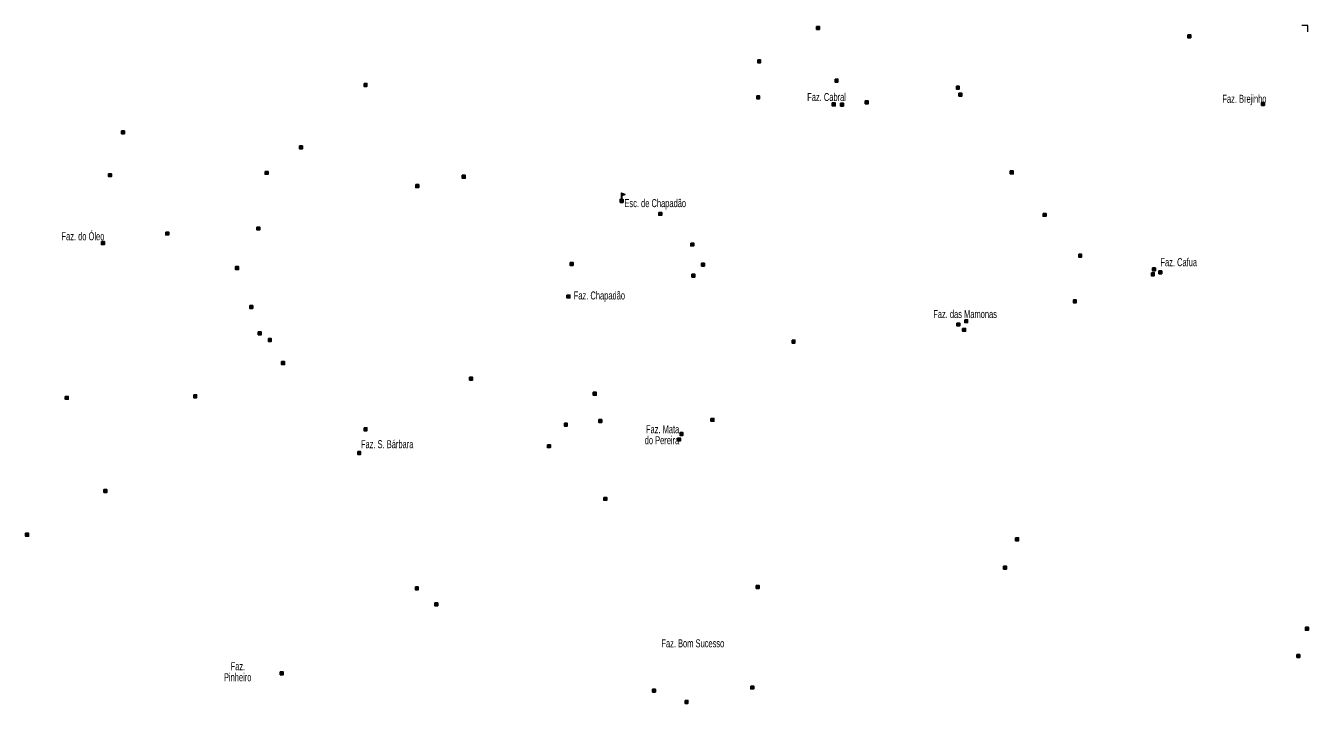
# Model space of a CAD drawing. Extents: x 447.8 to 473.9, y 7733.1 to 7760.8.
# Drawn here: x 461.07 to 473.9, y 7754.02 to 7760.8 of the extents above; entities that cross this region are included whole.
import ezdxf
from ezdxf.enums import TextEntityAlignment as Align

# ---------------------------------------------------------------- set-up
doc = ezdxf.new("R2010")
doc.units = 0
doc.header["$LTSCALE"] = 0.032
for name, color, linetype, lineweight in [('2', 7, 'Continuous', 25), ('4', 7, 'Continuous', 25), ('63', 7, 'Continuous', 13)]:
    doc.layers.add(name, color=color, linetype=linetype, lineweight=lineweight)
doc.layers.add('61', color=7, linetype='Continuous')

msp = doc.modelspace()

# ---------------------------------------------------------------- hatches: boundary and pattern name
at = {"layer": '2'}
for points in [[(468.9794, 7760.7919), (469.0084, 7760.7919), (469.0084, 7760.7629), (468.9794, 7760.7629)], [(472.691, 7760.7083), (472.72, 7760.7083), (472.72, 7760.6793), (472.691, 7760.6793)], [(468.3912, 7760.4577), (468.4202, 7760.4577), (468.4202, 7760.4287), (468.3912, 7760.4287)], [(469.1648, 7760.2655), (469.1938, 7760.2655), (469.1938, 7760.2365), (469.1648, 7760.2365)], [(464.4566, 7760.222), (464.4856, 7760.222), (464.4856, 7760.193), (464.4566, 7760.193)], [(470.3778, 7760.195), (470.4068, 7760.195), (470.4068, 7760.166), (470.3778, 7760.166)], [(468.382, 7760.0984), (468.411, 7760.0984), (468.411, 7760.0694), (468.382, 7760.0694)], [(469.1373, 7760.0274), (469.1663, 7760.0274), (469.1663, 7759.9984), (469.1373, 7759.9984)], [(469.2197, 7760.0251), (469.2487, 7760.0251), (469.2487, 7759.9961), (469.2197, 7759.9961)], [(469.4669, 7760.048), (469.4959, 7760.048), (469.4959, 7760.019), (469.4669, 7760.019)], [(470.4034, 7760.1247), (470.4324, 7760.1247), (470.4324, 7760.0957), (470.4034, 7760.0957)], [(473.4281, 7760.0321), (473.4571, 7760.0321), (473.4571, 7760.0031), (473.4281, 7760.0031)], [(462.0327, 7759.7482), (462.0617, 7759.7482), (462.0617, 7759.7192), (462.0327, 7759.7192)], [(463.8112, 7759.5971), (463.8402, 7759.5971), (463.8402, 7759.5681), (463.8112, 7759.5681)], [(461.9023, 7759.3202), (461.9313, 7759.3202), (461.9313, 7759.2912), (461.9023, 7759.2912)], [(463.4679, 7759.3431), (463.4969, 7759.3431), (463.4969, 7759.3141), (463.4679, 7759.3141)], [(465.4386, 7759.3041), (465.4676, 7759.3041), (465.4676, 7759.2751), (465.4386, 7759.2751)], [(470.9167, 7759.3473), (470.9457, 7759.3473), (470.9457, 7759.3183), (470.9167, 7759.3183)], [(464.9739, 7759.2103), (465.0029, 7759.2103), (465.0029, 7759.1813), (464.9739, 7759.1813)], [(467.4024, 7758.9334), (467.4314, 7758.9334), (467.4314, 7758.9044), (467.4024, 7758.9044)], [(471.2447, 7758.9234), (471.2737, 7758.9234), (471.2737, 7758.8944), (471.2447, 7758.8944)], [(462.4745, 7758.7365), (462.5035, 7758.7365), (462.5035, 7758.7075), (462.4745, 7758.7075)], [(463.3855, 7758.7869), (463.4145, 7758.7869), (463.4145, 7758.7579), (463.3855, 7758.7579)], [(461.8313, 7758.6404), (461.8603, 7758.6404), (461.8603, 7758.6114), (461.8313, 7758.6114)], [(467.7228, 7758.6266), (467.7518, 7758.6266), (467.7518, 7758.5976), (467.7228, 7758.5976)], [(471.6004, 7758.5145), (471.6294, 7758.5145), (471.6294, 7758.4855), (471.6004, 7758.4855)], [(463.1726, 7758.3909), (463.2016, 7758.3909), (463.2016, 7758.3619), (463.1726, 7758.3619)], [(466.5166, 7758.4321), (466.5456, 7758.4321), (466.5456, 7758.4031), (466.5166, 7758.4031)], [(467.8304, 7758.4252), (467.8594, 7758.4252), (467.8594, 7758.3962), (467.8304, 7758.3962)], [(472.3374, 7758.3781), (472.3664, 7758.3781), (472.3664, 7758.3491), (472.3374, 7758.3491)], [(472.4013, 7758.3483), (472.4303, 7758.3483), (472.4303, 7758.3193), (472.4013, 7758.3193)], [(467.7343, 7758.3154), (467.7633, 7758.3154), (467.7633, 7758.2864), (467.7343, 7758.2864)], [(472.3268, 7758.3292), (472.3558, 7758.3292), (472.3558, 7758.3002), (472.3268, 7758.3002)], [(466.4846, 7758.1071), (466.5136, 7758.1071), (466.5136, 7758.0781), (466.4846, 7758.0781)], [(463.3145, 7758.0018), (463.3435, 7758.0018), (463.3435, 7757.9728), (463.3145, 7757.9728)], [(471.5472, 7758.0587), (471.5762, 7758.0587), (471.5762, 7758.0297), (471.5472, 7758.0297)], [(470.3821, 7757.8265), (470.4111, 7757.8265), (470.4111, 7757.7975), (470.3821, 7757.7975)], [(470.4607, 7757.8602), (470.4897, 7757.8602), (470.4897, 7757.8312), (470.4607, 7757.8312)], [(463.3992, 7757.7386), (463.4282, 7757.7386), (463.4282, 7757.7096), (463.3992, 7757.7096)], [(470.4396, 7757.7732), (470.4686, 7757.7732), (470.4686, 7757.7442), (470.4396, 7757.7442)], [(463.4999, 7757.6722), (463.5289, 7757.6722), (463.5289, 7757.6432), (463.4999, 7757.6432)], [(468.7345, 7757.6562), (468.7635, 7757.6562), (468.7635, 7757.6272), (468.7345, 7757.6272)], [(463.6327, 7757.441), (463.6617, 7757.441), (463.6617, 7757.412), (463.6327, 7757.412)], [(465.5118, 7757.2854), (465.5408, 7757.2854), (465.5408, 7757.2564), (465.5118, 7757.2564)], [(461.4697, 7757.0931), (461.4987, 7757.0931), (461.4987, 7757.0641), (461.4697, 7757.0641)], [(462.7537, 7757.1091), (462.7827, 7757.1091), (462.7827, 7757.0801), (462.7537, 7757.0801)], [(466.7478, 7757.1343), (466.7768, 7757.1343), (466.7768, 7757.1053), (466.7478, 7757.1053)], [(466.4594, 7756.8253), (466.4884, 7756.8253), (466.4884, 7756.7963), (466.4594, 7756.7963)], [(466.8027, 7756.8619), (466.8317, 7756.8619), (466.8317, 7756.8329), (466.8027, 7756.8329)], [(467.9243, 7756.8734), (467.9533, 7756.8734), (467.9533, 7756.8444), (467.9243, 7756.8444)], [(464.4566, 7756.7795), (464.4856, 7756.7795), (464.4856, 7756.7505), (464.4566, 7756.7505)], [(467.5901, 7756.6765), (467.6191, 7756.6765), (467.6191, 7756.6475), (467.5901, 7756.6475)], [(467.6153, 7756.7315), (467.6443, 7756.7315), (467.6443, 7756.7025), (467.6153, 7756.7025)], [(464.3926, 7756.5415), (464.4216, 7756.5415), (464.4216, 7756.5125), (464.3926, 7756.5125)], [(466.29, 7756.6102), (466.319, 7756.6102), (466.319, 7756.5812), (466.29, 7756.5812)], [(461.8565, 7756.1616), (461.8855, 7756.1616), (461.8855, 7756.1326), (461.8565, 7756.1326)], [(466.8531, 7756.0837), (466.8821, 7756.0837), (466.8821, 7756.0547), (466.8531, 7756.0547)], [(461.0737, 7755.7244), (461.1027, 7755.7244), (461.1027, 7755.6954), (461.0737, 7755.6954)], [(470.97, 7755.6795), (470.999, 7755.6795), (470.999, 7755.6505), (470.97, 7755.6505)], [(470.8486, 7755.3962), (470.8776, 7755.3962), (470.8776, 7755.3672), (470.8486, 7755.3672)], [(464.9693, 7755.1888), (464.9983, 7755.1888), (464.9983, 7755.1598), (464.9693, 7755.1598)], [(468.3774, 7755.2025), (468.4064, 7755.2025), (468.4064, 7755.1735), (468.3774, 7755.1735)], [(465.1639, 7755.0286), (465.1929, 7755.0286), (465.1929, 7754.9996), (465.1639, 7754.9996)], [(473.8667, 7754.7849), (473.8957, 7754.7849), (473.8957, 7754.7559), (473.8667, 7754.7559)], [(473.7815, 7754.5123), (473.8105, 7754.5123), (473.8105, 7754.4833), (473.7815, 7754.4833)], [(463.6189, 7754.3396), (463.6479, 7754.3396), (463.6479, 7754.3106), (463.6189, 7754.3106)], [(467.3406, 7754.1657), (467.3696, 7754.1657), (467.3696, 7754.1367), (467.3406, 7754.1367)], [(468.3225, 7754.1977), (468.3515, 7754.1977), (468.3515, 7754.1687), (468.3225, 7754.1687)], [(467.6656, 7754.0535), (467.6946, 7754.0535), (467.6946, 7754.0245), (467.6656, 7754.0245)]]:
    msp.add_hatch(color=256, dxfattribs=at).paths.add_polyline_path(points)
at = {"layer": '4'}
msp.add_hatch(color=256, dxfattribs=at).paths.add_polyline_path([(467.0159, 7759.0334), (467.0159, 7759.0634), (467.0459, 7759.0634), (467.0459, 7759.0334)])

# ---------------------------------------------------------------- linework, layer by layer
at = {"layer": '2'}
for points in [[(468.9794, 7760.7919), (469.0084, 7760.7919), (469.0084, 7760.7629), (468.9794, 7760.7629)], [(472.691, 7760.7083), (472.72, 7760.7083), (472.72, 7760.6793), (472.691, 7760.6793)], [(468.3912, 7760.4577), (468.4202, 7760.4577), (468.4202, 7760.4287), (468.3912, 7760.4287)], [(469.1648, 7760.2655), (469.1938, 7760.2655), (469.1938, 7760.2365), (469.1648, 7760.2365)], [(464.4566, 7760.222), (464.4856, 7760.222), (464.4856, 7760.193), (464.4566, 7760.193)], [(470.3778, 7760.195), (470.4068, 7760.195), (470.4068, 7760.166), (470.3778, 7760.166)], [(468.382, 7760.0984), (468.411, 7760.0984), (468.411, 7760.0694), (468.382, 7760.0694)], [(469.1373, 7760.0274), (469.1663, 7760.0274), (469.1663, 7759.9984), (469.1373, 7759.9984)], [(469.2197, 7760.0251), (469.2487, 7760.0251), (469.2487, 7759.9961), (469.2197, 7759.9961)], [(469.4669, 7760.048), (469.4959, 7760.048), (469.4959, 7760.019), (469.4669, 7760.019)], [(470.4034, 7760.1247), (470.4324, 7760.1247), (470.4324, 7760.0957), (470.4034, 7760.0957)], [(473.4281, 7760.0321), (473.4571, 7760.0321), (473.4571, 7760.0031), (473.4281, 7760.0031)], [(462.0327, 7759.7482), (462.0617, 7759.7482), (462.0617, 7759.7192), (462.0327, 7759.7192)], [(463.8112, 7759.5971), (463.8402, 7759.5971), (463.8402, 7759.5681), (463.8112, 7759.5681)], [(461.9023, 7759.3202), (461.9313, 7759.3202), (461.9313, 7759.2912), (461.9023, 7759.2912)], [(463.4679, 7759.3431), (463.4969, 7759.3431), (463.4969, 7759.3141), (463.4679, 7759.3141)], [(465.4386, 7759.3041), (465.4676, 7759.3041), (465.4676, 7759.2751), (465.4386, 7759.2751)], [(470.9167, 7759.3473), (470.9457, 7759.3473), (470.9457, 7759.3183), (470.9167, 7759.3183)], [(464.9739, 7759.2103), (465.0029, 7759.2103), (465.0029, 7759.1813), (464.9739, 7759.1813)], [(467.4024, 7758.9334), (467.4314, 7758.9334), (467.4314, 7758.9044), (467.4024, 7758.9044)], [(471.2447, 7758.9234), (471.2737, 7758.9234), (471.2737, 7758.8944), (471.2447, 7758.8944)], [(462.4745, 7758.7365), (462.5035, 7758.7365), (462.5035, 7758.7075), (462.4745, 7758.7075)], [(463.3855, 7758.7869), (463.4145, 7758.7869), (463.4145, 7758.7579), (463.3855, 7758.7579)], [(461.8313, 7758.6404), (461.8603, 7758.6404), (461.8603, 7758.6114), (461.8313, 7758.6114)], [(467.7228, 7758.6266), (467.7518, 7758.6266), (467.7518, 7758.5976), (467.7228, 7758.5976)], [(471.6004, 7758.5145), (471.6294, 7758.5145), (471.6294, 7758.4855), (471.6004, 7758.4855)], [(463.1726, 7758.3909), (463.2016, 7758.3909), (463.2016, 7758.3619), (463.1726, 7758.3619)], [(466.5166, 7758.4321), (466.5456, 7758.4321), (466.5456, 7758.4031), (466.5166, 7758.4031)], [(467.8304, 7758.4252), (467.8594, 7758.4252), (467.8594, 7758.3962), (467.8304, 7758.3962)], [(472.3374, 7758.3781), (472.3664, 7758.3781), (472.3664, 7758.3491), (472.3374, 7758.3491)], [(472.4013, 7758.3483), (472.4303, 7758.3483), (472.4303, 7758.3193), (472.4013, 7758.3193)], [(467.7343, 7758.3154), (467.7633, 7758.3154), (467.7633, 7758.2864), (467.7343, 7758.2864)], [(472.3268, 7758.3292), (472.3558, 7758.3292), (472.3558, 7758.3002), (472.3268, 7758.3002)], [(466.4846, 7758.1071), (466.5136, 7758.1071), (466.5136, 7758.0781), (466.4846, 7758.0781)], [(463.3145, 7758.0018), (463.3435, 7758.0018), (463.3435, 7757.9728), (463.3145, 7757.9728)], [(471.5472, 7758.0587), (471.5762, 7758.0587), (471.5762, 7758.0297), (471.5472, 7758.0297)], [(470.3821, 7757.8265), (470.4111, 7757.8265), (470.4111, 7757.7975), (470.3821, 7757.7975)], [(470.4607, 7757.8602), (470.4897, 7757.8602), (470.4897, 7757.8312), (470.4607, 7757.8312)], [(463.3992, 7757.7386), (463.4282, 7757.7386), (463.4282, 7757.7096), (463.3992, 7757.7096)], [(470.4396, 7757.7732), (470.4686, 7757.7732), (470.4686, 7757.7442), (470.4396, 7757.7442)], [(463.4999, 7757.6722), (463.5289, 7757.6722), (463.5289, 7757.6432), (463.4999, 7757.6432)], [(468.7345, 7757.6562), (468.7635, 7757.6562), (468.7635, 7757.6272), (468.7345, 7757.6272)], [(463.6327, 7757.441), (463.6617, 7757.441), (463.6617, 7757.412), (463.6327, 7757.412)], [(465.5118, 7757.2854), (465.5408, 7757.2854), (465.5408, 7757.2564), (465.5118, 7757.2564)], [(461.4697, 7757.0931), (461.4987, 7757.0931), (461.4987, 7757.0641), (461.4697, 7757.0641)], [(462.7537, 7757.1091), (462.7827, 7757.1091), (462.7827, 7757.0801), (462.7537, 7757.0801)], [(466.7478, 7757.1343), (466.7768, 7757.1343), (466.7768, 7757.1053), (466.7478, 7757.1053)], [(466.4594, 7756.8253), (466.4884, 7756.8253), (466.4884, 7756.7963), (466.4594, 7756.7963)], [(466.8027, 7756.8619), (466.8317, 7756.8619), (466.8317, 7756.8329), (466.8027, 7756.8329)], [(467.9243, 7756.8734), (467.9533, 7756.8734), (467.9533, 7756.8444), (467.9243, 7756.8444)], [(464.4566, 7756.7795), (464.4856, 7756.7795), (464.4856, 7756.7505), (464.4566, 7756.7505)], [(467.5901, 7756.6765), (467.6191, 7756.6765), (467.6191, 7756.6475), (467.5901, 7756.6475)], [(467.6153, 7756.7315), (467.6443, 7756.7315), (467.6443, 7756.7025), (467.6153, 7756.7025)], [(464.3926, 7756.5415), (464.4216, 7756.5415), (464.4216, 7756.5125), (464.3926, 7756.5125)], [(466.29, 7756.6102), (466.319, 7756.6102), (466.319, 7756.5812), (466.29, 7756.5812)], [(461.8565, 7756.1616), (461.8855, 7756.1616), (461.8855, 7756.1326), (461.8565, 7756.1326)], [(466.8531, 7756.0837), (466.8821, 7756.0837), (466.8821, 7756.0547), (466.8531, 7756.0547)], [(461.0737, 7755.7244), (461.1027, 7755.7244), (461.1027, 7755.6954), (461.0737, 7755.6954)], [(470.97, 7755.6795), (470.999, 7755.6795), (470.999, 7755.6505), (470.97, 7755.6505)], [(470.8486, 7755.3962), (470.8776, 7755.3962), (470.8776, 7755.3672), (470.8486, 7755.3672)], [(464.9693, 7755.1888), (464.9983, 7755.1888), (464.9983, 7755.1598), (464.9693, 7755.1598)], [(468.3774, 7755.2025), (468.4064, 7755.2025), (468.4064, 7755.1735), (468.3774, 7755.1735)], [(465.1639, 7755.0286), (465.1929, 7755.0286), (465.1929, 7754.9996), (465.1639, 7754.9996)], [(473.8667, 7754.7849), (473.8957, 7754.7849), (473.8957, 7754.7559), (473.8667, 7754.7559)], [(473.7815, 7754.5123), (473.8105, 7754.5123), (473.8105, 7754.4833), (473.7815, 7754.4833)], [(463.6189, 7754.3396), (463.6479, 7754.3396), (463.6479, 7754.3106), (463.6189, 7754.3106)], [(467.3406, 7754.1657), (467.3696, 7754.1657), (467.3696, 7754.1367), (467.3406, 7754.1367)], [(468.3225, 7754.1977), (468.3515, 7754.1977), (468.3515, 7754.1687), (468.3225, 7754.1687)], [(467.6656, 7754.0535), (467.6946, 7754.0535), (467.6946, 7754.0245), (467.6656, 7754.0245)]]:
    msp.add_lwpolyline(points, close=True, dxfattribs=at)
at = {"layer": '4'}
msp.add_line((467.0284, 7759.0634), (467.0334, 7759.0634), dxfattribs=at)
for points in [[(467.0284, 7759.0634), (467.0284, 7759.1259), (467.0634, 7759.1134), (467.0334, 7759.1029), (467.0334, 7759.0634)], [(467.0159, 7759.0334), (467.0159, 7759.0634), (467.0459, 7759.0634), (467.0459, 7759.0334)]]:
    msp.add_lwpolyline(points, close=True, dxfattribs=at)
at = {"layer": '63'}
msp.add_lwpolyline([(473.8909, 7760.7385), (473.8909, 7760.8001), (473.8302, 7760.8001)], dxfattribs=at)

# ---------------------------------------------------------------- texts
at = {"layer": '61', "width": 0.7}
for s, p in [('Faz. Cabral', (469.2733, 7760.0466)), ('Faz. Brejinho', (473.4772, 7760.0288)), ('Faz. do Óleo', (461.8608, 7758.6543)), ('Faz. Mata', (467.6074, 7756.7252)), ('do Pereira', (467.6074, 7756.6152)), ('Faz.   ', (463.3304, 7754.3554)), ('Pinheiro', (463.3304, 7754.2454))]:
    msp.add_text(s, height=0.08, dxfattribs=at).set_placement(p, align=Align.RIGHT)
for s, p in [('Esc. de Chapadão', (467.0591, 7758.9855)), ('Faz. Cafua', (472.4168, 7758.3952)), ('Faz. Chapadão', (466.5528, 7758.0625)), ('Faz. das Mamonas', (470.146, 7757.8766)), ('Faz. S. Bárbara', (464.425, 7756.5757)), ('Faz. Bom Sucesso', (467.4286, 7754.5846))]:
    msp.add_text(s, height=0.08, dxfattribs=at).set_placement(p)

doc.saveas('drawing.dxf')
